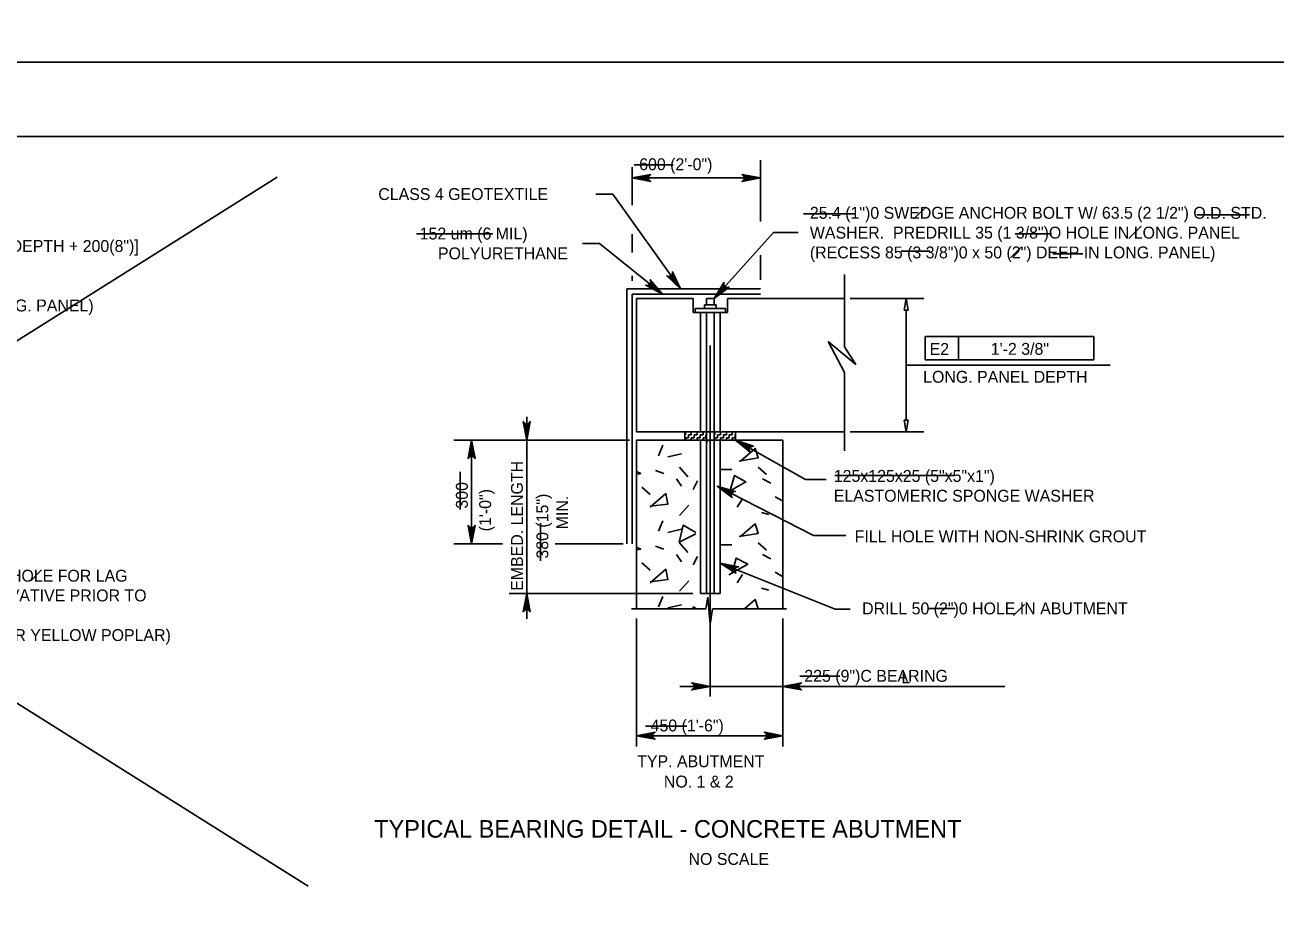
# Model space of a CAD drawing. Extents: x 179 to 454, y -271 to 54.
# Drawn here: x 254.79 to 267.41, y -118.53 to -109.62 of the extents above; entities that cross this region are included whole.
import ezdxf

# ---------------------------------------------------------------- set-up
doc = ezdxf.new("R2010")
doc.units = 0
for name, color, linetype in [('Level 1', 7, 'Continuous'), ('Level 2', 7, 'Continuous'), ('Level 3', 7, 'Continuous'), ('Level 4', 7, 'Continuous'), ('Level 41', 7, 'Continuous'), ('Level 63', 7, 'Continuous')]:
    doc.layers.add(name, color=color, linetype=linetype)

msp = doc.modelspace()

# ---------------------------------------------------------------- linework, layer by layer
at = {"layer": 'Level 1'}
msp.add_lwpolyline([(245.497, -131.25), (276.997, -131.25), (276.997, -110.75), (245.497, -110.75)], close=True, dxfattribs=at)
at = {"layer": 'Level 2'}
for p, q in [((260.862, -112.286), (260.862, -114.86)), ((260.862, -112.286), (262.21, -112.286)), ((260.916, -112.34), (260.916, -114.86)), ((260.916, -112.34), (262.21, -112.34)), ((260.96, -112.384), (260.96, -113.731)), ((260.96, -112.384), (261.529, -112.384)), ((261.529, -112.526), (261.529, -112.384)), ((261.664, -112.384), (261.743, -112.384)), ((261.664, -112.384), (261.664, -112.447)), ((261.743, -112.384), (261.743, -112.447)), ((261.877, -112.526), (261.877, -112.384)), ((261.877, -112.384), (263.053, -112.384)), ((261.529, -112.526), (261.877, -112.526)), ((261.55, -112.486), (261.857, -112.486)), ((261.55, -112.526), (261.55, -112.486)), ((261.605, -113.731), (261.605, -112.526)), ((261.644, -112.486), (261.644, -112.447)), ((261.644, -112.447), (261.762, -112.447)), ((261.664, -112.526), (261.664, -115.36)), ((261.743, -112.526), (261.743, -115.36)), ((261.762, -112.486), (261.762, -112.447)), ((261.802, -113.731), (261.802, -112.526)), ((261.857, -112.526), (261.857, -112.486)), ((261.703, -112.599), (261.703, -112.599)), ((260.96, -113.731), (263.053, -113.731)), ((260.96, -113.814), (262.436, -113.814)), ((260.96, -113.814), (260.96, -115.516)), ((261.447, -113.731), (261.447, -113.814)), ((261.447, -113.76), (261.453, -113.76)), ((261.453, -113.76), (261.453, -113.731)), ((261.453, -113.79), (261.482, -113.79)), ((261.453, -113.814), (261.453, -113.79)), ((261.482, -113.76), (261.512, -113.76)), ((261.482, -113.79), (261.482, -113.76)), ((261.512, -113.76), (261.512, -113.731)), ((261.512, -113.79), (261.541, -113.79)), ((261.512, -113.814), (261.512, -113.79)), ((261.541, -113.76), (261.571, -113.76)), ((261.541, -113.79), (261.541, -113.76)), ((261.571, -113.76), (261.571, -113.731)), ((261.571, -113.79), (261.6, -113.79)), ((261.571, -113.814), (261.571, -113.79)), ((261.6, -113.76), (261.63, -113.76)), ((261.6, -113.79), (261.6, -113.76)), ((261.605, -115.36), (261.605, -113.814)), ((261.63, -113.76), (261.63, -113.731)), ((261.63, -113.79), (261.659, -113.79)), ((261.63, -113.814), (261.63, -113.79)), ((261.659, -113.76), (261.664, -113.76)), ((261.659, -113.79), (261.659, -113.76)), ((261.743, -113.76), (261.748, -113.76)), ((261.748, -113.76), (261.748, -113.731)), ((261.748, -113.79), (261.777, -113.79)), ((261.748, -113.814), (261.748, -113.79)), ((261.777, -113.76), (261.807, -113.76)), ((261.777, -113.79), (261.777, -113.76)), ((261.802, -115.36), (261.802, -113.814)), ((261.807, -113.76), (261.807, -113.731)), ((261.807, -113.79), (261.836, -113.79)), ((261.807, -113.814), (261.807, -113.79)), ((261.836, -113.76), (261.866, -113.76)), ((261.836, -113.79), (261.836, -113.76)), ((261.866, -113.76), (261.866, -113.731)), ((261.866, -113.79), (261.895, -113.79)), ((261.866, -113.814), (261.866, -113.79)), ((261.895, -113.76), (261.925, -113.76)), ((261.895, -113.79), (261.895, -113.76)), ((261.925, -113.76), (261.925, -113.731)), ((261.925, -113.79), (261.954, -113.79)), ((261.925, -113.814), (261.925, -113.79)), ((261.954, -113.76), (261.959, -113.76)), ((261.954, -113.79), (261.954, -113.76)), ((261.959, -113.731), (261.959, -113.814)), ((262.436, -113.814), (262.436, -115.516)), ((261.605, -115.36), (261.802, -115.36)), ((261.659, -115.516), (261.678, -115.4)), ((261.678, -115.4), (261.701, -115.67)), ((260.907, -115.516), (261.659, -115.516)), ((261.701, -115.67), (261.726, -115.516)), ((261.726, -115.516), (262.472, -115.516))]:
    msp.add_line(p, q, dxfattribs=at)
at = {"layer": 'Level 3'}
for p, q in [((262.21, -111.607), (262.21, -110.988)), ((260.916, -111.442), (260.916, -111.061)), ((262.21, -111.168), (260.916, -111.168)), ((260.719, -111.331), (260.55, -111.331)), ((263.758, -111.582), (263.882, -111.459)), ((265.925, -111.78), (266.049, -111.656)), ((260.916, -111.919), (260.916, -111.736)), ((262.34, -111.72), (262.591, -111.72)), ((260.586, -111.829), (260.413, -111.829)), ((264.732, -111.974), (264.839, -111.868)), ((262.211, -112.197), (262.211, -111.947)), ((260.916, -112.207), (260.916, -112.157)), ((263.058, -112.141), (263.058, -112.872)), ((263.116, -112.384), (263.859, -112.384)), ((263.679, -112.504), (263.679, -113.611)), ((262.891, -112.82), (263.058, -113.132)), ((263.172, -113.049), (262.891, -112.82)), ((263.872, -112.768), (265.573, -112.768)), ((263.872, -113.004), (263.872, -112.768)), ((264.207, -113.004), (264.207, -112.768)), ((265.573, -112.768), (265.573, -113.004)), ((261.703, -112.859), (261.703, -116.402)), ((263.058, -112.872), (263.172, -113.049)), ((263.679, -113.057), (265.739, -113.057)), ((265.573, -113.004), (263.872, -113.004)), ((263.058, -113.132), (263.058, -113.923)), ((259.852, -113.814), (259.852, -113.578)), ((260.461, -113.814), (259.116, -113.814)), ((259.296, -113.814), (259.296, -114.86)), ((260.887, -113.814), (259.675, -113.814)), ((259.852, -113.814), (259.852, -115.36)), ((261.678, -113.814), (261.668, -113.834)), ((263.116, -113.731), (263.859, -113.731)), ((261.223, -113.866), (261.181, -113.972)), ((261.414, -113.951), (261.276, -113.982)), ((261.149, -114.12), (261.234, -114.152)), ((261.361, -114.205), (261.414, -114.279)), ((261.393, -114.088), (261.478, -114.184)), ((261.806, -114.109), (261.922, -114.109)), ((262.187, -114.088), (262.272, -114.162)), ((262.229, -114.205), (262.314, -114.247)), ((261.012, -114.289), (261.096, -114.364)), ((261.573, -114.226), (261.53, -114.311)), ((262.664, -114.212), (262.871, -114.212)), ((261.975, -114.491), (262.028, -114.406)), ((262.357, -114.385), (262.431, -114.427)), ((261.488, -114.47), (261.393, -114.575)), ((262.219, -114.544), (262.293, -114.565)), ((261.223, -114.628), (261.181, -114.734)), ((261.414, -114.713), (261.276, -114.745)), ((262.745, -114.777), (263.07, -114.777)), ((259.608, -114.86), (259.116, -114.86)), ((260.826, -114.86), (260.138, -114.86)), ((261.149, -114.883), (261.234, -114.914)), ((261.361, -114.967), (261.414, -115.041)), ((261.393, -114.851), (261.478, -114.946)), ((261.806, -114.872), (261.922, -114.872)), ((262.187, -114.851), (262.272, -114.925)), ((262.229, -114.967), (262.314, -115.01)), ((261.012, -115.052), (261.096, -115.126)), ((261.573, -114.988), (261.53, -115.073)), ((254.848, -115.232), (254.956, -115.124)), ((261.975, -115.253), (262.028, -115.168)), ((262.357, -115.147), (262.431, -115.19)), ((261.488, -115.232), (261.393, -115.338)), ((262.219, -115.306), (262.293, -115.327)), ((261.528, -115.36), (259.675, -115.36)), ((259.852, -115.36), (259.852, -115.596)), ((261.223, -115.391), (261.181, -115.497)), ((259.852, -115.596), (259.852, -115.618)), ((261.414, -115.476), (261.276, -115.507)), ((262.962, -115.52), (263.113, -115.52)), ((264.761, -115.585), (264.874, -115.473)), ((260.96, -115.615), (260.96, -116.904)), ((262.436, -115.615), (262.436, -116.904)), ((262.436, -116.159), (262.436, -116.354)), ((261.703, -116.299), (261.397, -116.299)), ((261.663, -116.299), (262.673, -116.299)), ((262.673, -116.299), (264.676, -116.299)), ((262.436, -116.796), (260.96, -116.796))]:
    msp.add_line(p, q, dxfattribs=at)
for points in [[(260.916, -111.168), (261.102, -111.133), (261.088, -111.143), (261.081, -111.156), (261.079, -111.168), (261.081, -111.181), (261.088, -111.193), (261.102, -111.203), (260.916, -111.168), (261.088, -111.193), (261.081, -111.181), (260.916, -111.168), (261.079, -111.168), (261.081, -111.156), (260.916, -111.168), (261.088, -111.143)], [(262.21, -111.168), (262.024, -111.203), (262.038, -111.193), (262.046, -111.181), (262.048, -111.168), (262.046, -111.156), (262.038, -111.143), (262.024, -111.133), (262.21, -111.168), (262.038, -111.143), (262.046, -111.156), (262.21, -111.168), (262.048, -111.168), (262.046, -111.181), (262.21, -111.168), (262.038, -111.193)], [(261.402, -112.286), (260.719, -111.331)], [(261.743, -112.384), (262.34, -111.72)], [(261.22, -112.34), (260.586, -111.829)], [(261.402, -112.286), (261.266, -112.155), (261.282, -112.161), (261.296, -112.159), (261.308, -112.154), (261.317, -112.145), (261.323, -112.132), (261.322, -112.114), (261.402, -112.286), (261.323, -112.132), (261.317, -112.145), (261.402, -112.286), (261.308, -112.154), (261.296, -112.159), (261.402, -112.286), (261.282, -112.161)], [(261.22, -112.34), (261.053, -112.251), (261.071, -112.252), (261.084, -112.247), (261.094, -112.238), (261.1, -112.227), (261.102, -112.213), (261.097, -112.196), (261.22, -112.34), (261.102, -112.213), (261.1, -112.227), (261.22, -112.34), (261.094, -112.238), (261.084, -112.247), (261.22, -112.34), (261.071, -112.252)], [(261.743, -112.384), (261.841, -112.222), (261.839, -112.239), (261.844, -112.253), (261.851, -112.263), (261.862, -112.27), (261.876, -112.273), (261.893, -112.269), (261.743, -112.384), (261.876, -112.273), (261.862, -112.27), (261.743, -112.384), (261.851, -112.263), (261.844, -112.253), (261.743, -112.384), (261.839, -112.239)], [(259.852, -113.814), (259.817, -113.627), (259.827, -113.642), (259.839, -113.649), (259.852, -113.651), (259.864, -113.649), (259.877, -113.642), (259.887, -113.627), (259.852, -113.814), (259.877, -113.642), (259.864, -113.649), (259.852, -113.814), (259.852, -113.651), (259.839, -113.649), (259.852, -113.814), (259.827, -113.642)], [(259.296, -113.814), (259.331, -114), (259.321, -113.986), (259.309, -113.978), (259.296, -113.976), (259.284, -113.978), (259.271, -113.986), (259.261, -114), (259.296, -113.814), (259.271, -113.986), (259.284, -113.978), (259.296, -113.814), (259.296, -113.976), (259.309, -113.978), (259.296, -113.814), (259.321, -113.986)], [(261.959, -113.814), (262.664, -114.212)], [(261.959, -113.814), (262.139, -113.875), (262.121, -113.877), (262.109, -113.884), (262.101, -113.894), (262.096, -113.906), (262.097, -113.92), (262.104, -113.936), (261.959, -113.814), (262.097, -113.92), (262.096, -113.906), (261.959, -113.814), (262.101, -113.894), (262.109, -113.884), (261.959, -113.814), (262.121, -113.877)], [(261.996, -114.025), (262.187, -113.993), (262.155, -113.898), (262.007, -114.025)], [(260.96, -114.16), (261.001, -114.152), (260.96, -114.131)], [(261.872, -114.342), (262.062, -114.236), (261.946, -114.172), (261.903, -114.321)], [(261.773, -114.278), (262.745, -114.776)], [(261.773, -114.278), (261.955, -114.332), (261.937, -114.334), (261.925, -114.342), (261.917, -114.352), (261.914, -114.364), (261.914, -114.379), (261.923, -114.394), (261.773, -114.278), (261.914, -114.379), (261.914, -114.364), (261.773, -114.278), (261.917, -114.352), (261.925, -114.342), (261.773, -114.278), (261.937, -114.334)], [(261.096, -114.48), (261.276, -114.459), (261.255, -114.353), (261.096, -114.491)], [(259.296, -114.86), (259.261, -114.674), (259.271, -114.688), (259.284, -114.696), (259.296, -114.698), (259.309, -114.696), (259.321, -114.688), (259.331, -114.674), (259.296, -114.86), (259.321, -114.688), (259.309, -114.696), (259.296, -114.86), (259.296, -114.698), (259.284, -114.696), (259.296, -114.86), (259.271, -114.688)], [(261.558, -114.758), (261.389, -114.842), (261.431, -114.673), (261.558, -114.747)], [(261.996, -114.787), (262.187, -114.755), (262.155, -114.66), (262.007, -114.787)], [(260.96, -114.922), (261.001, -114.914), (260.96, -114.894)], [(261.802, -115.054), (262.962, -115.52)], [(261.802, -115.054), (261.988, -115.091), (261.971, -115.095), (261.959, -115.104), (261.953, -115.115), (261.95, -115.127), (261.952, -115.142), (261.962, -115.156), (261.802, -115.054), (261.952, -115.142), (261.95, -115.127), (261.802, -115.054), (261.953, -115.115), (261.959, -115.104), (261.802, -115.054), (261.971, -115.095)], [(261.891, -115.173), (262.081, -115.067), (261.965, -115.004), (261.923, -115.152)], [(261.096, -115.243), (261.276, -115.221), (261.255, -115.116), (261.096, -115.253)], [(259.852, -115.36), (259.887, -115.546), (259.877, -115.532), (259.864, -115.524), (259.852, -115.522), (259.839, -115.524), (259.827, -115.532), (259.817, -115.546), (259.852, -115.36), (259.827, -115.532), (259.839, -115.524), (259.852, -115.36), (259.852, -115.522), (259.864, -115.524), (259.852, -115.36), (259.877, -115.532)], [(262.186, -115.516), (262.155, -115.423), (262.047, -115.516)], [(261.526, -115.516), (261.53, -115.497), (261.563, -115.516)], [(261.703, -116.299), (261.517, -116.334), (261.531, -116.324), (261.539, -116.312), (261.541, -116.299), (261.539, -116.287), (261.531, -116.274), (261.517, -116.264), (261.703, -116.299), (261.531, -116.274), (261.539, -116.287), (261.703, -116.299), (261.541, -116.299), (261.539, -116.312), (261.703, -116.299), (261.531, -116.324)], [(262.436, -116.299), (262.623, -116.264), (262.608, -116.274), (262.601, -116.287), (262.599, -116.299), (262.601, -116.312), (262.608, -116.324), (262.623, -116.334), (262.436, -116.299), (262.608, -116.324), (262.601, -116.312), (262.436, -116.299), (262.599, -116.299), (262.601, -116.287), (262.436, -116.299), (262.608, -116.274)], [(260.96, -116.796), (261.146, -116.762), (261.132, -116.772), (261.125, -116.784), (261.122, -116.796), (261.125, -116.809), (261.132, -116.822), (261.146, -116.831), (260.96, -116.796), (261.132, -116.822), (261.125, -116.809), (260.96, -116.796), (261.122, -116.796), (261.125, -116.784), (260.96, -116.796), (261.132, -116.772)], [(262.436, -116.796), (262.25, -116.831), (262.264, -116.822), (262.272, -116.809), (262.274, -116.796), (262.272, -116.784), (262.264, -116.772), (262.25, -116.762), (262.436, -116.796), (262.264, -116.772), (262.272, -116.784), (262.436, -116.796), (262.274, -116.796), (262.272, -116.809), (262.436, -116.796), (262.264, -116.822)]]:
    msp.add_lwpolyline(points, dxfattribs=at)
for points in [[(261.036, -111.148), (261.036, -111.188), (260.916, -111.168)], [(262.09, -111.148), (262.09, -111.188), (262.21, -111.168)], [(261.402, -112.286), (261.341, -112.183), (261.325, -112.194)], [(261.22, -112.34), (261.133, -112.257), (261.12, -112.273)], [(261.743, -112.384), (261.83, -112.301), (261.815, -112.288)], [(263.659, -112.504), (263.699, -112.504), (263.679, -112.384)], [(259.832, -113.696), (259.871, -113.696), (259.852, -113.814)], [(263.659, -113.611), (263.699, -113.611), (263.679, -113.731)], [(259.276, -113.934), (259.316, -113.934), (259.296, -113.814)], [(259.276, -114.74), (259.316, -114.74), (259.296, -114.86)], [(259.832, -115.478), (259.871, -115.478), (259.852, -115.36)], [(261.545, -116.28), (261.545, -116.319), (261.663, -116.299)], [(262.554, -116.28), (262.554, -116.319), (262.436, -116.299)], [(261.078, -116.777), (261.078, -116.816), (260.96, -116.796)], [(262.318, -116.777), (262.318, -116.816), (262.436, -116.796)]]:
    msp.add_lwpolyline(points, close=True, dxfattribs=at)
at = {"layer": 'Level 41'}
for p, q in [((260.937, -111.036), (261.329, -111.036)), ((257.335, -111.161), (245.957, -118.316)), ((246.267, -111.161), (257.645, -118.316)), ((262.643, -111.529), (263.161, -111.529)), ((266.611, -111.542), (267.142, -111.542)), ((258.739, -111.731), (259.51, -111.731)), ((264.779, -111.731), (265.145, -111.731)), ((263.629, -111.908), (263.919, -111.908)), ((265.158, -111.934), (265.461, -111.934)), ((259.181, -114.513), (259.181, -114.134)), ((262.959, -114.172), (264.16, -114.172)), ((259.99, -115.031), (259.99, -114.652)), ((263.894, -115.512), (264.172, -115.512)), ((262.605, -116.195), (263.01, -116.195)), ((261.051, -116.7), (261.468, -116.7))]:
    msp.add_line(p, q, dxfattribs=at)
at = {"layer": 'Level 63'}
for points in [[(243.747, -110), (277.747, -110), (277.747, -88), (243.747, -88)], [(243.747, -132), (277.747, -132), (277.747, -110), (243.747, -110)]]:
    msp.add_lwpolyline(points, close=True, dxfattribs=at)

# ---------------------------------------------------------------- texts
at = {"layer": 'Level 2'}
msp.add_text('TYPICAL BEARING DETAIL - CONCRETE ABUTMENT', height=0.17717, dxfattribs=at).set_placement((258.313, -117.825))
at = {"layer": 'Level 3'}
for s, p in [('600 (2\'-0")', (260.986, -111.09)), ('CLASS 4 GEOTEXTILE', (258.354, -111.391)), ('25.4 (1")0 SWEDGE ANCHOR BOLT W/ 63.5 (2 1/2") O.D. STD.', (262.708, -111.58)), ('152 um (6 MIL)', (258.772, -111.789)), ('WASHER.  PREDRILL 35 (1 3/8")O HOLE IN LONG. PANEL', (262.708, -111.78)), ('19.1(3/4") 0 LAG SCREW [LENGTH = PANEL DEPTH + 200(8")]', (251.311, -111.915)), ('POLYURETHANE', (258.956, -111.989)), ('(RECESS 85 (3 3/8")0 x 50 (2") DEEP IN LONG. PANEL)', (262.708, -111.98)), ('(RECESS 85 (3 3/8") O x 25 (1") DEEP IN LONG. PANEL)', (251.311, -112.515)), ('E2', (263.916, -112.954)), ('LONG. PANEL DEPTH', (263.851, -113.235)), ('FILL HOLE WITH NON-SHRINK GROUT', (263.16, -114.845)), ('FIELD DRILL 14.3 (9/16") 0 PILOT HOLE FOR LAG', (252.12, -115.242)), ('SCREW AND FILL WITH PRESERVATIVE PRIOR TO', (252.12, -115.441)), ('DRILL 50 (2")0 HOLE IN ABUTMENT', (263.235, -115.572)), ('(USE 12.7 (1/2") 0 PILOT HOLE FOR YELLOW POPLAR)', (252.12, -115.841)), ('225 (9")C BEARING', (262.652, -116.252)), ('L', (263.632, -116.268)), ('450 (1\'-6")', (261.101, -116.753)), ('TYP. ABUTMENT', (260.966, -117.114)), ('NO. 1 & 2', (261.235, -117.319)), ('NO SCALE', (261.484, -118.1))]:
    msp.add_text(s, height=0.12, dxfattribs=at).set_placement(p)
for s, p in [('EMBED. LENGTH', (259.813, -115.334)), ('300', (259.257, -114.505)), ('(1\'-0")', (259.492, -114.734)), ('380 (15")', (260.069, -115.009)), ('MIN.', (260.269, -114.714))]:
    msp.add_text(s, height=0.12, rotation=90, dxfattribs=at).set_placement(p)
at = {"layer": 'Level 4'}
for s, p in [('125x125x25 (5"x5"x1")', (262.949, -114.235)), ('ELASTOMERIC SPONGE WASHER', (262.949, -114.435))]:
    msp.add_text(s, height=0.12, dxfattribs=at).set_placement(p)
at = {"layer": 'Level 41'}
msp.add_text('1\'-2 3/8"', height=0.12, dxfattribs=at).set_placement((264.533, -112.953))

doc.saveas('drawing.dxf')
